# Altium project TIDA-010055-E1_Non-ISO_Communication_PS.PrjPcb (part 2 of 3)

## Sheet TIDA-010055-E1_Non-ISO_Communication_PS_Pg4.SchDoc
size 431 x 279 mm; Date: Not shown in title block; ApprovedBy: Not shown in title block; CheckedBy: Not shown in title block; Author: Not shown in title block; CompanyName: Not shown in title block; Engineer: Not shown in title block; Organization: Not shown in title block; Address1: Not shown in title block; Address2: Not shown in title block; Address3: Not shown in title block; Address4: Not shown in title block; DocumentNumber: 1; Revision: Use project parameter SCH_Rev; SheetNumber: 4; SheetTotal: 7; PageSetup: Record=PageOptions¦CenterHorizontal=True¦CenterVertical=True¦PrintScale=1.00¦XCorrection=1.00¦YCorrection=1.00¦PrintKind=0¦BorderSize=5000000¦LeftOffset=0¦BottomOffset=0¦Orientation=2¦PaperLength=1000¦PaperWidth=1000¦Scale=100¦PaperSource=15¦PrintQuality=600¦MediaType=1¦DitherType=10¦PaperKind=Letter¦PrintScaleMode=1
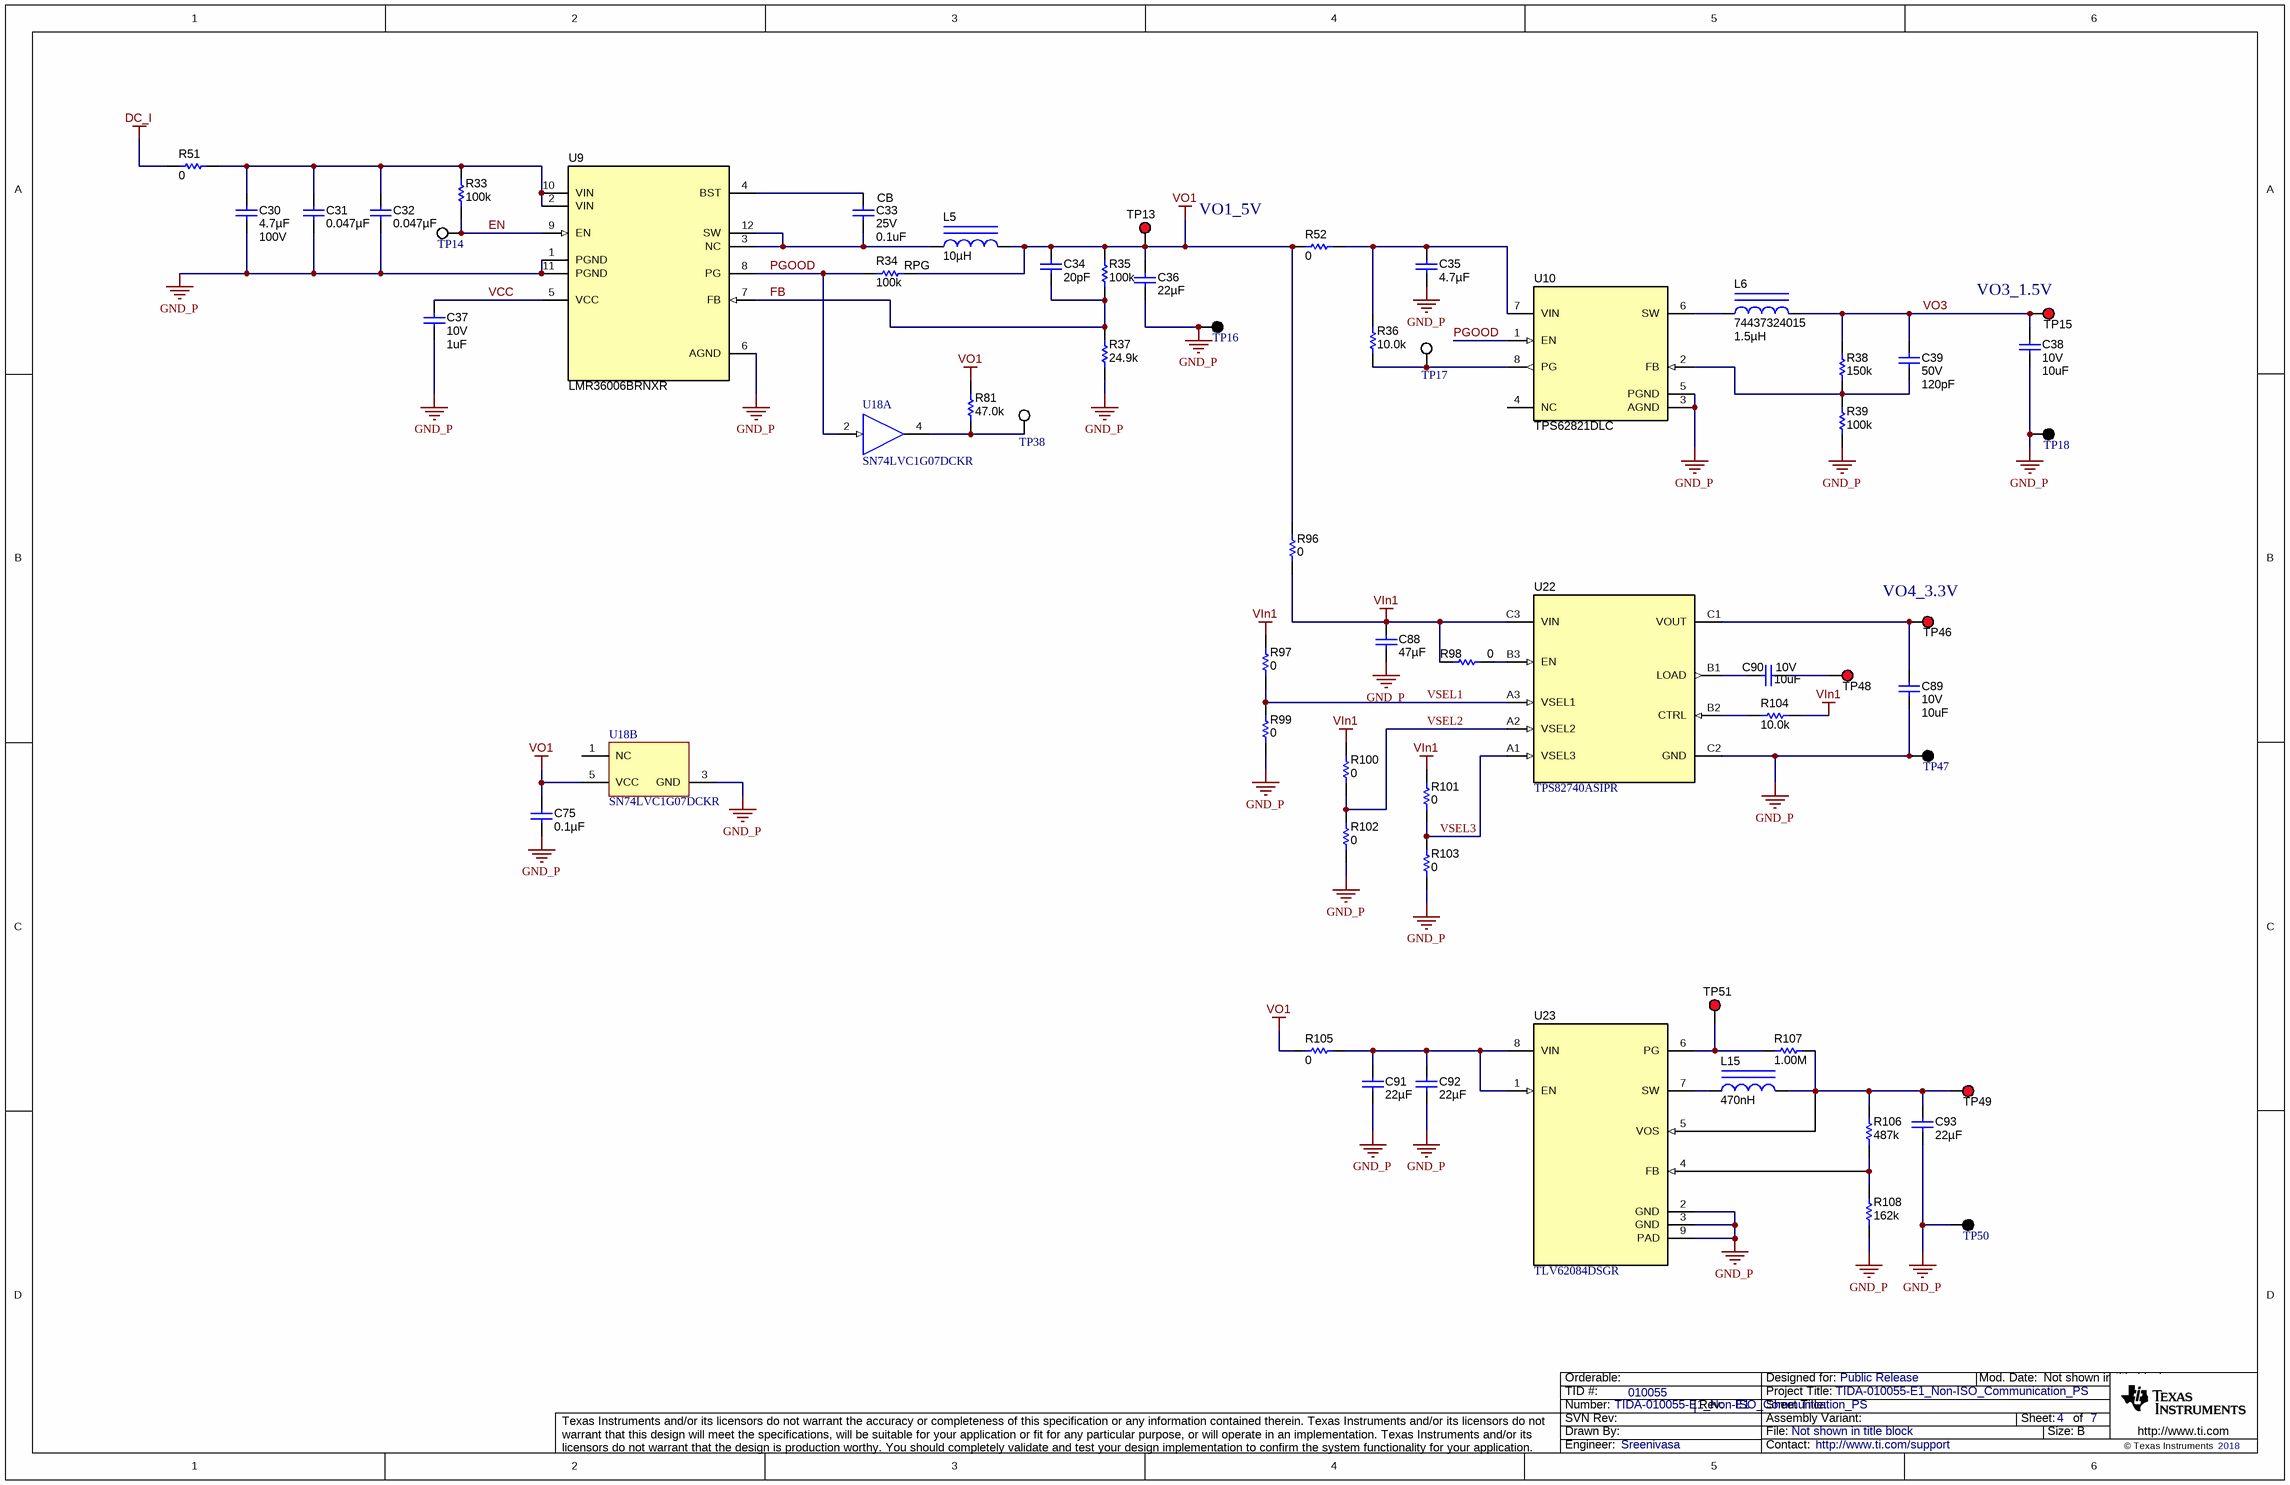
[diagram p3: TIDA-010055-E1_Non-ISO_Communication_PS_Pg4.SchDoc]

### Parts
C30  ValueDisplayed: 4.7µF  Value2: 100V  [1210_220L]  (hidden comment: CIN2)
C31  ValueDisplayed: 0.047µF  [0603L]  (hidden comment: CIN3)
C32  ValueDisplayed: 0.047µF  [0603L]  (hidden comment: CIN1)
C33  CB  VDC_V: 25V  ValueDisplayed: 0.1uF  [0402L]
C34  ValueDisplayed: 20pF  [0402L]  (hidden comment: CFF)
C35  ValueDisplayed: 4.7µF  [0805_HV]  (hidden comment: C2012X7R1A475M125AC)
C36  ValueDisplayed: 22µF  [0805_HV1]  (hidden comment: CL21A226KQCLRNC)
C37  VDC_V: 10V  ValueDisplayed: 1uF  [0402]  (hidden comment: C1005X7S1A105K050BC)
C38  VDC_V: 10V  ValueDisplayed: 10uF  [0805L]  (hidden comment: GRM21BR71A106ME51L)
C39  VDC_V: 50V  ValueDisplayed: 120pF  [0402]  (hidden comment: GRM1555C1H121FA01D)
C75  ValueDisplayed: 0.1µF  [0603]  (hidden comment: C0603C104K5RECAUTO)
C88  ValueDisplayed: 47µF  [1206_190L]  (hidden comment: CL31A476MPHNNNE)
C89  VDC_V: 10V  ValueDisplayed: 10uF  [0805L]  (hidden comment: GRM21BR71A106ME51L)
C90  VDC_V: 10V  ValueDisplayed: 10uF  [0805L]  (hidden comment: GRM21BR71A106ME51L)
C91  ValueDisplayed: 22µF  [0805_HV]  (hidden comment: JMK212BJ226KG-T)
C92  ValueDisplayed: 22µF  [0805_HV]  (hidden comment: JMK212BJ226KG-T)
C93  ValueDisplayed: 22µF  [0805_HV]  (hidden comment: JMK212BJ226KG-T)
L5  ValueDisplayed: 10µH  [WE-MAPI_4030]  (hidden comment: 74438357100)
L6  74437324015  ValueDisplayed: 1.5µH  [IND_WE-LHMI-4020]
L15  ValueDisplayed: 470nH  [VLS2012ET]  (hidden comment: VLS2012ET-R47N)
R33  ValueDisplayed: 100k  [0402L]  (hidden comment: CRCW0402100KFKED)
R34  RPG  ValueDisplayed: 100k  [0402L]
R35  ValueDisplayed: 100k  [0402L]  (hidden comment: CRCW0402100KFKED)
R36  ValueDisplayed: 10.0k  [0402L]  (hidden comment: RPG2)
R37  ValueDisplayed: 24.9k  [0402L]  (hidden comment: CRCW040224K9FKED)
R38  ValueDisplayed: 150k  [0402]  (hidden comment: ERJ-2RKF1503X)
R39  ValueDisplayed: 100k  [0402L]  (hidden comment: RFBB2)
R51  ValueDisplayed: 0  [5108]  (hidden comment: 5108)
R52  ValueDisplayed: 0  [5108]  (hidden comment: 5108)
R81  ValueDisplayed: 47.0k  [0603]  (hidden comment: RG1608P-473-B-T5)
R96  ValueDisplayed: 0  [5108]  (hidden comment: 5108)
R97  ValueDisplayed: 0  [0603]  (hidden comment: CRCW06030000Z0EA)
R98  ValueDisplayed: 0  [0603]  (hidden comment: CRCW06030000Z0EA)
R99  ValueDisplayed: 0  [0603]  (hidden comment: CRCW06030000Z0EA)
R100  ValueDisplayed: 0  [0603]  (hidden comment: CRCW06030000Z0EA)
R101  ValueDisplayed: 0  [0603]  (hidden comment: CRCW06030000Z0EA)
R102  ValueDisplayed: 0  [0603]  (hidden comment: CRCW06030000Z0EA)
R103  ValueDisplayed: 0  [0603]  (hidden comment: CRCW06030000Z0EA)
R104  ValueDisplayed: 10.0k  [0402L]  (hidden comment: RPG2)
R105  ValueDisplayed: 0  [5108]  (hidden comment: 5108)
R106  ValueDisplayed: 487k  [0402]  (hidden comment: CRCW0402487KFKED)
R107  ValueDisplayed: 1.00M  [0402L]  (hidden comment: RC0402FR-071ML)
R108  ValueDisplayed: 162k  [0603L]  (hidden comment: RC0603FR-07162KL)
TP13  5000  [Keystone5000]  (value not drawn)
TP14  5002  [Keystone5002]  (value not drawn)
TP15  5000  [Keystone5000]  (value not drawn)
TP16  5001  [Keystone5001]  (value not drawn)
TP17  5002  [Keystone5002]  (value not drawn)
TP18  5001  [Keystone5001]  (value not drawn)
TP38  5002  [Keystone5002]  (value not drawn)
TP46  5000  [Keystone5000]  (value not drawn)
TP47  5001  [Keystone5001]  (value not drawn)
TP48  5000  [Keystone5000]  (value not drawn)
TP49  5000  [Keystone5000]  (value not drawn)
TP50  5001  [Keystone5001]  (value not drawn)
TP51  5000  [Keystone5000]  (value not drawn)
U9  LMR36006BRNXR  [RNX0012B]
U10  TPS62821DLC  [DLC0008A]
U18  SN74LVC1G07DCKR  [DCK0005A_N]  (parts A,B of 2)
U22  TPS82740ASIPR  [SIP0009F]
U23  TLV62084DSGR  [DSG0008A]

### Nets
DC_I: R51.2
GND_P: C30.1 C31.2 C32.2 C35.2 C36.2 C37.2 C38.2 C75.2 C88.2 C89.2 C91.2 C92.2 C93.2 R37.1 R39.1 R99.1 R102.1 R103.1 R108.1 TP16.1 TP18.1 TP47.1 TP50.1 U9.1(PGND) U9.6(AGND) U9.11(PGND) U10.3(AGND) U10.5(PGND) U18.3(GND) U22.C2(GND) U23.2(GND) U23.3(GND) U23.9(PAD)
VIn1: C88.1 R96.2 R97.2 R98.1 R100.2 R101.2 R104.1 U22.C3(VIN)
VO1: C34.1 C36.1 C75.1 L5.2 R34.1 R35.2 R52.2 R81.2 R96.1 R105.1 TP13.1 U18.5(VCC)
EN: R33.1 TP14.1 U9.9(EN)
FB: C34.2 R35.1 R37.2 U9.7(FB)
PGOOD: R34.2 U9.8(PG) U10.1(EN) U18.2(A)
VCC: C37.1 U9.5(VCC)
VO3: C38.1 C39.1 L6.2 R38.2 TP15.1
VSEL1: R97.1 R99.2 U22.A3(VSEL1)
VSEL2: R100.1 R102.2 U22.A2(VSEL2)
VSEL3: R101.1 R103.2 U22.A1(VSEL3)
NetC30_2: C30.2 C31.1 C32.1 R33.2 R51.1 U9.2(VIN) U9.10(VIN)
NetC33_1: C33.1 U9.4(BST)
NetC33_2: C33.2 L5.1 U9.3(NC) U9.12(SW)
NetC35_1: C35.1 R36.2 R52.1 U10.7(VIN)
NetC39_2: C39.2 R38.1 R39.2 U10.2(FB)
NetC89_1: C89.1 TP46.1 U22.C1(VOUT)
NetC90_1: C90.1 U22.B1(LOAD)
NetC90_2: C90.2 TP48.1
NetC91_1: C91.1 C92.1 R105.2 U23.1(EN) U23.8(VIN)
NetC93_1: C93.1 L15.2 R106.2 R107.2 TP49.1 U23.5(VOS)
NetL6_1: L6.1 U10.6(SW)
NetL15_1: L15.1 U23.7(SW)
NetR36_1: R36.1 TP17.1 U10.8(PG)
NetR81_1: R81.1 TP38.1 U18.4(Y)
NetR98_2: R98.2 U22.B3(EN)
NetR104_2: R104.2 U22.B2(CTRL)
NetR106_1: R106.1 R108.2 U23.4(FB)
NetR107_1: R107.1 TP51.1 U23.6(PG)

Not connected (* = marked no-connect by the designer): U10 4(NC); U18 1(NC)

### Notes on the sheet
- VO1_5V
- (near TP15) VO3_1.5V
- (near TP46) VO4_3.3V

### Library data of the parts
C30 = CGA6M3X7S2A475K200AB: CAP, CERM, 4.7 µF, 100 V, +/- 10%, X7S, AEC-Q200 Grade 1, 1210; Manufacturer: TDK; Polarized: N; CompType: Capacitor; Value: 4.7uF; U/M: EA; Cap_F: 0.0000047; Tolerance_%: 10; ESR_ohm: 0.004236; Value1: 0.004236 ohm; VDC_V: 100; IRMS_A: 3.57337; TaMin_C: -55; TaMax_C: 125; Cap_Case: 1210_220; SizeArea_mm2: 8; SizeAreaWB_mm2: 14.7; SizeX_mm: 3.2; SizeY_mm: 2.5; SizeZ_mm: 2.2; AEC Category: Q200; AEC Qualified: Y; AEC Grade: 1
C31 C32 = CGA3E3X7S2A473K080AB: CAP, CERM, 0.047 µF, 100 V,+/- 10%, X7S, AEC-Q200 Grade 1, 0603; Manufacturer: TDK; Polarized: N; CompType: Capacitor; Value: 0.047uF; U/M: EA; Cap_F: 0.000000047; Tolerance_%: 10; ESR_ohm: 0.089796; Value1: 0.089796 ohm; VDC_V: 100; Value2: 100V; IRMS_A: 0.567484; TaMin_C: -55; TaMax_C: 125; Cap_Case: 0603; SizeArea_mm2: 1.28; SizeAreaWB_mm2: 4.68; SizeX_mm: 1.6; SizeY_mm: 0.8; SizeZ_mm: 1; AEC Category: Q200; AEC Qualified: Y
C33 = CMP-0006659-2: CAP, CERM, 0.1 uF, 25 V, +/- 10%, X7R, 0402; Manufacturer: MuRata; PartNumber: GRM155R71E104KE14D; TaMin_C: -55°C; Polarized: N; SizeAreaWB_mm2: 3; Value1: Unknown; U/M: EA; Value: 0.1uF; TaMax_C: 125°C; SizeZ_mm: 0.6; SizeX_mm: 1; SizeY_mm: 0.5; Cap_Case: 0402; CompType: Capacitor; Cap_F: 100nF; AEC Category: Q200
C34 = GRM1555C1E200JA01D: CAP, CERM, 20 pF, 25 V,+/- 5%, C0G/NP0, 0402; Manufacturer: MuRata; Polarized: N; CompType: Capacitor; Value: 20pF; U/M: EA; Cap_F: 0.00000000002; Tolerance_%: 5; VDC_V: 25; Value2: 25V; TaMin_C: -55; TaMax_C: 125; Cap_Case: 0402; SizeArea_mm2: 0.5; SizeAreaWB_mm2: 3; SizeX_mm: 1; SizeZ_mm: 0.6; AEC Category: Q200
C35 = C2012X7R1A475M125AC: CAP, CERM, 4.7 µF, 10 V,+/- 20%, X7R, 0805; Manufacturer: TDK; Polarized: N; CompType: Capacitor; Value: 4.7uF; U/M: EA; Cap_F: 0.0000047; Tolerance_%: 20; VDC_V: 10; Value2: 10V; TaMin_C: -55; TaMax_C: 125; Cap_Case: 0805; SizeArea_mm2: 2.5; SizeAreaWB_mm2: 6.75; SizeX_mm: 2; SizeY_mm: 1.25; SizeZ_mm: 1.45; AEC Category: Q200; Green_Lifecycle: Active; Green_REACh: Passed
C36 = GRM21BR60J226ME39L: CAP, CERM, 22 µF, 6.3 V, +/- 20%, X5R, 0805; Manufacturer: Samsung Electro-Mechanics; Polarized: N; CompType: Capacitor; Value: 22uF; U/M: EA; Cap_F: 0.000022; Tolerance_%: 20; ESR_ohm: 0.009; Value1: 0.009 ohm; VDC_V: 6.3; Value2: 6.3V; IRMS_A: 3.5; TaMin_C: -55; TaMax_C: 85; Cap_Case: 0805; AEC Category: Q200
C37 = CMP-0006300-2: CAP, CERM, 1 uF, 10 V, +/- 10%, X7S, 0402; Manufacturer: Murata Electronics North America; PartNumber: GCM155C71A105KE38D; TaMin_C: -55°C; ESR_ohm: 0.011416; Polarized: N; SizeAreaWB_mm2: 3; Value1: 0.011416 ohm; U/M: EA; Value: 1uF; TaMax_C: 125°C; SizeZ_mm: 0.6; SizeX_mm: 1; SizeY_mm: 0.5; CompType: Capacitor; Cap_F: 1µF; IRMS_A: 1.483A; AEC Category: Q200
C38 C89 C90 = CMP-0008316-2: CAP, CERM, 10 uF, 10 V, +/- 20%, X7R, 0805; Manufacturer: TDK Corporation; PartNumber: C2012X7R1A106M125AC; TaMin_C: -55°C; Polarized: N; SizeAreaWB_mm2: 6.75; Value1: Unknown; U/M: EA; Value: 10uF; TaMax_C: 125°C; SizeZ_mm: 1.45; SizeX_mm: 2; SizeY_mm: 1.25; Cap_Case: 0805; SizeArea_mm2: 2.5; CompType: Capacitor; Cap_F: 10µF; AEC Category: Q200
C39 = CMP-0006416-2: CAP, CERM, 120 pF, 50 V, +/- 1%, C0G/NP0, 0402; Manufacturer: Samsung Electro-Mechanics; PartNumber: CL05C121JB5NNNC; TaMin_C: -55°C; Polarized: N; SizeAreaWB_mm2: 3; Value1: Unknown; U/M: EA; Value: 120pF; TaMax_C: 125°C; SizeZ_mm: 0.6; SizeX_mm: 1; SizeY_mm: 0.5; CompType: Capacitor; AEC Category: Q200
C75 = C0603C104K5RACTU: CAP, CERM, 0.1µF ±10% 50V Ceramic Capacitor X7R 0603; Manufacturer: Kemet; Polarized: N; Value: 0.1uF; U/M: EA; Cap_F: 0.0000001; Tolerance_%: 10; VDC_V: 50; TaMin_C: -55; TaMax_C: 125; SizeArea_mm2: 1.28; SizeAreaWB_mm2: 4.68; SizeX_mm: 1.6; SizeY_mm: 0.8; SizeZ_mm: 1; AEC Category: Q200; Green_Lifecycle: Active; Green_REACh: Passed
C88 = C3216X5R1E476M160AC: CAP, CERM, 47 µF, 25 V,+/- 20%, X5R, 1206; Manufacturer: Samsung Electro-Mechanics; Polarized: N; CompType: Capacitor; Value: 47uF; U/M: EA; Cap_F: 0.000047; Tolerance_%: 20; VDC_V: 25; Value2: 25V; TaMin_C: -55; TaMax_C: 85; Cap_Case: 1206; SizeArea_mm2: 5.12; SizeAreaWB_mm2: 10.92; SizeX_mm: 3.2; SizeY_mm: 1.6; SizeZ_mm: 1.9; AEC Category: Q200; Green_Lifecycle: Active; Green_REACh: Passed
C91-C93 = JMK212BJ226KG-T: CAP, CERM, 22 µF, 6.3 V,+/- 10%, X5R, 0805; Manufacturer: Taiyo Yuden; Polarized: N; CompType: Capacitor; Value: 22uF; U/M: EA; Cap_F: 0.000022; Tolerance_%: 10; ESR_ohm: 0.002; Value1: 0.002 ohm; VDC_V: 6.3; Value2: 6.3V; TaMin_C: -55; TaMax_C: 85; Cap_Case: 0805; AEC Category: Q200; SizeArea_mm2: 2.5; SizeAreaWB_mm2: 6.75; SizeX_mm: 2; SizeY_mm: 1.25; SizeZ_mm: 1.45; Green_Lifecycle: Not Set; Green_REACh: Incomplete
L5 = CMP-0081728-1: Inductor, Shielded, Metal Composite, 10 µH, 2.7 A, 0.11 ohm, SMD; Manufacturer: Wurth Elektronik; SizeAreaWB_mm2: 26.01; Irms: 2.7A @ 40C rise; SizeArea_mm2: 16.81; AEC Qualified: N; AEC Category: Q200; Value: 10uH; SizeZ_mm: 3.1; Imax_A: 2.7A; SizeY_mm: 4.1; Isat: 4.6A @ 20% inductance drop; DCR_ohm: 0.11
L6 = 74437324015: Inductor, Shielded Drum Core, Powdered Iron, 1.5uH, 3.8A, 0.0348 ohm, SMD; Manufacturer: Wurth Elektronik eiSos; Ind_H: 1.5E-6; Imax_A: 3.8; Irms: 3.8A @ 40C rise; Isat: 8A @ 20% inductance drop; DCR_ohm: 0.0348; U/M: EA
L15 = VLS2012ET-R47N: Inductor, Shielded Drum Core, Ferrite, 470 nH, 2 A, 0.059 ohm, SMD; Manufacturer: TDK; Value: 470nH; Ind_H: 470.0E-9; Imax_A: 2; Irms: 2A @ 40C rise; Isat: 2.25A @ 30% inductance drop; DCR_ohm: 0.059; Value2: 2A; AEC Category: Q200
R33-R35 = CRCW0402100KFKED: RES, 100 k, 1%, 0.063 W, 0402; Manufacturer: Vishay-Dale; CompType: Resistor; Value: 100k; Res_ohm: 100000; Tolerance_%: 1; Power_W: 0.063; Value2: 0.063W; VDC_V: 50; TempCo: 100 ppm/C; SizeArea_mm2: 0.5; SizeZ_mm: 0.6; EIA_Code: E96; U/M: EA; AEC Category: Q200; Green_Lifecycle: Active; Green_REACh: Passed
R36 R104 = CMP-0025958-2: RES, 10.0 k, 1%, 0.063 W, 0402; Manufacturer: Vishay-Dale; PartNumber: CRCW040210K0FKED; Power_W: 63mW; TempCo: 100 ppm/C; Value_Code: 10k0; U/M: EA; Value: 10.0k; EIA_Code: E96; Res_ohm: 10k; SizeX_mm: 1; SizeY_mm: 0.5; SizeZ_mm: 0.6; Value2: 0.063W; CompType: Resistor; VDC_V: 50V; AEC Category: Q200
R37 = CMP-0026196-1: RES, 24.9 k, 1%, 0.063 W, 0402; Manufacturer: Vishay-Dale; Power_W: 63mW; TempCo: 100 ppm/C; Value_Code: 24k9; U/M: EA; Value: 24.9k; EIA_Code: E96; SizeX_mm: 1; SizeY_mm: 0.5; SizeZ_mm: 0.6; Value2: 0.063W; CompType: Resistor; VDC_V: 50V; AEC Category: Q200
R38 = CMP-0026669-1: RES, 150 k, 1%, 0.1 W, AEC-Q200 Grade 0, 0402; Manufacturer: Panasonic; Power_W: 100mW; TempCo: 100 ppm/C; U/M: EA; Value: 150k; EIA_Code: E96; SizeX_mm: 1; SizeY_mm: 0.5; SizeZ_mm: 0.6; Value2: 0.1W; CompType: Resistor; AEC Qualified: Y; VDC_V: 50V; AEC Grade: 0; AEC Category: Q200
R39 = CMP-0025950-2: RES, 100 k, 1%, 0.063 W, 0402; Manufacturer: Vishay-Dale; PartNumber: CRCW0402100KFKED; Power_W: 63mW; TempCo: 100 ppm/C; U/M: EA; Value: 100k; EIA_Code: E96; SizeX_mm: 1; SizeY_mm: 0.5; SizeZ_mm: 0.6; Value2: 0.063W; CompType: Resistor; VDC_V: 50V; AEC Category: Q200
R51 R52 R96 R105 = 5108: RES, 0, 1%, 0.5 W, 1206; Manufacturer: Keystone; CompType: Resistor; Value: 0; Tolerance_%: 1; Power_W: 0.5; Value2: 0.5W; TempCo: ppm/C; SizeArea_mm2: 5.185; SizeX_mm: 3.05; SizeY_mm: 1.7; SizeZ_mm: 0.84; U/M: EA; AEC Category: Q200; AEC Qualified: N
R81 = RG1608P-473-B-T5: RES, 47.0 k, 0.1%, 0.1 W, 0603; Manufacturer: Susumu Co Ltd; CompType: Resistor; Value: 47.0k; Res_ohm: 47000; Value_Code: 47k0; Tolerance_%: 0.1; Value2: 0.1W; VDC_V: 75; TempCo: 25 ppm/C; SizeArea_mm2: 1.28; SizeX_mm: 1.6; SizeY_mm: 0.8; SizeZ_mm: 1; EIA_Code: E192; U/M: EA; AEC Category: Q200
R97-R103 = CRCW06030000Z0EA: RES, 0, 5%, 0.1 W, 0603; Manufacturer: Vishay-Dale; CompType: Resistor; Value: 0; Value_Code: 0000; Tolerance_%: 5; Power_W: 0.1; Value2: 0.1W; VDC_V: 75; TempCo: 200 ppm/C; EIA_Code: E24; U/M: EA; AEC Category: Q200
R106 = CRCW0402487KFKED: RES, 487 k, 1%, 0.063 W, 0402; Manufacturer: Vishay-Dale; CompType: Resistor; Value: 487k; Res_ohm: 487000; Tolerance_%: 1; Power_W: 0.063; Value2: 0.063W; VDC_V: 50; TempCo: 100 ppm/C; SizeArea_mm2: 0.5; SizeZ_mm: 0.6; EIA_Code: E96; U/M: EA; AEC Category: Q200; Green_Lifecycle: Active; Green_REACh: Passed
R107 = RC0402FR-071ML: RES, 1.00 M, 1%, 0.063 W, 0402; Manufacturer: Yageo America; CompType: Resistor; Value: 1.00Meg; Res_ohm: 1000000; Value_Code: 1M00; Tolerance_%: 1; Power_W: 0.063; Value2: 0.063W; TempCo: 100 ppm/C; EIA_Code: E96; U/M: EA; AEC Category: Q200; SizeArea_mm2: 0.5; SizeZ_mm: 0.6; Green_Lifecycle: Active; Green_REACh: Passed
R108 = RC0603FR-07162KL: RES, 162 k, 1%, 0.1 W, 0603; Manufacturer: Yageo America; CompType: Resistor; Value: 162k; Res_ohm: 162000; Tolerance_%: 1; Power_W: 0.1; Value2: 0.1W; VDC_V: 150; TempCo: 200 ppm/C; EIA_Code: E96; U/M: EA; AEC Category: Q200; SizeArea_mm2: 1.28; SizeX_mm: 1.6; SizeY_mm: 0.8; Green_Lifecycle: Active; Green_REACh: Passed
TP13 TP15 TP46 TP48 TP49 TP51 = 5000: Test Point, Miniature, Red, TH; Manufacturer: Keystone; CompType: Test Point Loop; ContactFinish: Silver
TP14 TP17 TP38 = 5002: Test Point, Miniature, White, TH; Manufacturer: Keystone; CompType: Test Point Loop; ContactFinish: Silver; Green_Lifecycle: Active; Green_REACh: Passed
TP16 TP18 TP47 TP50 = 5001: Test Point, Miniature, Black, TH; Manufacturer: Keystone; CompType: Test Point Loop; ContactFinish: Silver; Green_Lifecycle: Active; Green_REACh: Passed
U9 = CMP-0077274-3: 65-V 0.6-A Synchronous Step-Down Converter, RNX0012B (VQFN-HR-12); Alternate PartNumber: LMR36006BRNXT; Alternate Manufacturer: Texas Instruments; SizeAreaWB_mm2: 12.0; SizeZ_mm: 1.0; SizeX_mm: 2.0; SizeY_mm: 3.0; SizeArea_mm2: 6.0; CompType: IC; AEC Qualified: N; AEC Category: Q200
U10 = CMP-0065148-2: 2.5-V to 5.5-V, 1-, 2-, 3-A Step-Down Converter with DCS-Control, DLC0008A (SON-HR-8); Manufacturer: Texas Instruments; SizeX_mm: 1.5; SizeY_mm: 2.0; CompType: IC; SizeZ_mm: 1.0; SizeArea_mm2: 3.0; SizeAreaWB_mm2: 7.5; U/M: EA
U18 = CMP-0051390-2: Single Buffer/Driver With Open-Drain Output, DCK0005A, LARGE T&R; Manufacturer: Texas Instruments; 3-State Output: No; F @ Nom Voltage(Max)(Mhz): 150; ICC @ Nom Voltage(Max)(mA): 0.01; VCC(Min)(V): 1.65; Logic: True; Sub-Family: Non-Inverting Buffer/Driver; Output Drive (IOL/IOH)(Max)(mA): 32/-32; Input Type: CMOS/TTL; Technology Family: LVC; Bits(#): 1; VCC(Max)(V): 5.5; Output Type: CMOS; tpd @ Nom Voltage(Max)(ns): 8.6,6,4.7,4; Rating: Catalog; Voltage(Nom)(V): 1.8,2.5,3.3,5; AEC Category: Q200; AEC Qualified: N; CompType: IC; SizeAreaWB_mm2: 9.3; SizeArea_mm2: 4.2; SizeX_mm: 2.1; SizeY_mm: 2.0; SizeZ_mm: 1.1
U22 = CMP-0067293-1: 200-mA Step Down Converter MicroSiP Module with 360nA quiescent current, SIP0009F (uSIP-9); Alternate PartNumber: TPS82740ASIPT; Alternate Manufacturer: Texas Instruments; SizeAreaWB_mm2: 13.2325; U/M: EA; SizeZ_mm: 1.1; SizeX_mm: 2.95; SizeY_mm: 2.35; SizeArea_mm2: 6.9325; CompType: IC
U23 = CMP-0067001-2: 2A High Efficient Step Down Converter in 2x2mm SON Package, TLV62084, DSG0008A (WSON-8); Alternate PartNumber: TLV62084DSGT; Manufacturer: Texas Instruments; SizeZ_mm: 0.8; SizeX_mm: 2.0; SizeArea_mm2: 4.0; CompType: IC; U/M: EA; SizeAreaWB_mm2: 9.0

## Sheet TIDA-010055-E1_Non-ISO_Communication_PS_Pg5.SchDoc
size 431 x 279 mm; Date: Not shown in title block; ApprovedBy: Not shown in title block; CheckedBy: Not shown in title block; Author: Not shown in title block; CompanyName: Not shown in title block; Engineer: Not shown in title block; Organization: Not shown in title block; Address1: Not shown in title block; Address2: Not shown in title block; Address3: Not shown in title block; Address4: Not shown in title block; DocumentNumber: 1; Revision: Use project parameter SCH_Rev; SheetNumber: 5; SheetTotal: 7; PageSetup: Record=PageOptions¦CenterHorizontal=True¦CenterVertical=True¦PrintScale=1.00¦XCorrection=1.00¦YCorrection=1.00¦PrintKind=0¦BorderSize=5000000¦LeftOffset=0¦BottomOffset=0¦Orientation=2¦PaperLength=1000¦PaperWidth=1000¦Scale=100¦PaperSource=15¦PrintQuality=600¦MediaType=1¦DitherType=10¦PaperKind=Letter¦PrintScaleMode=1
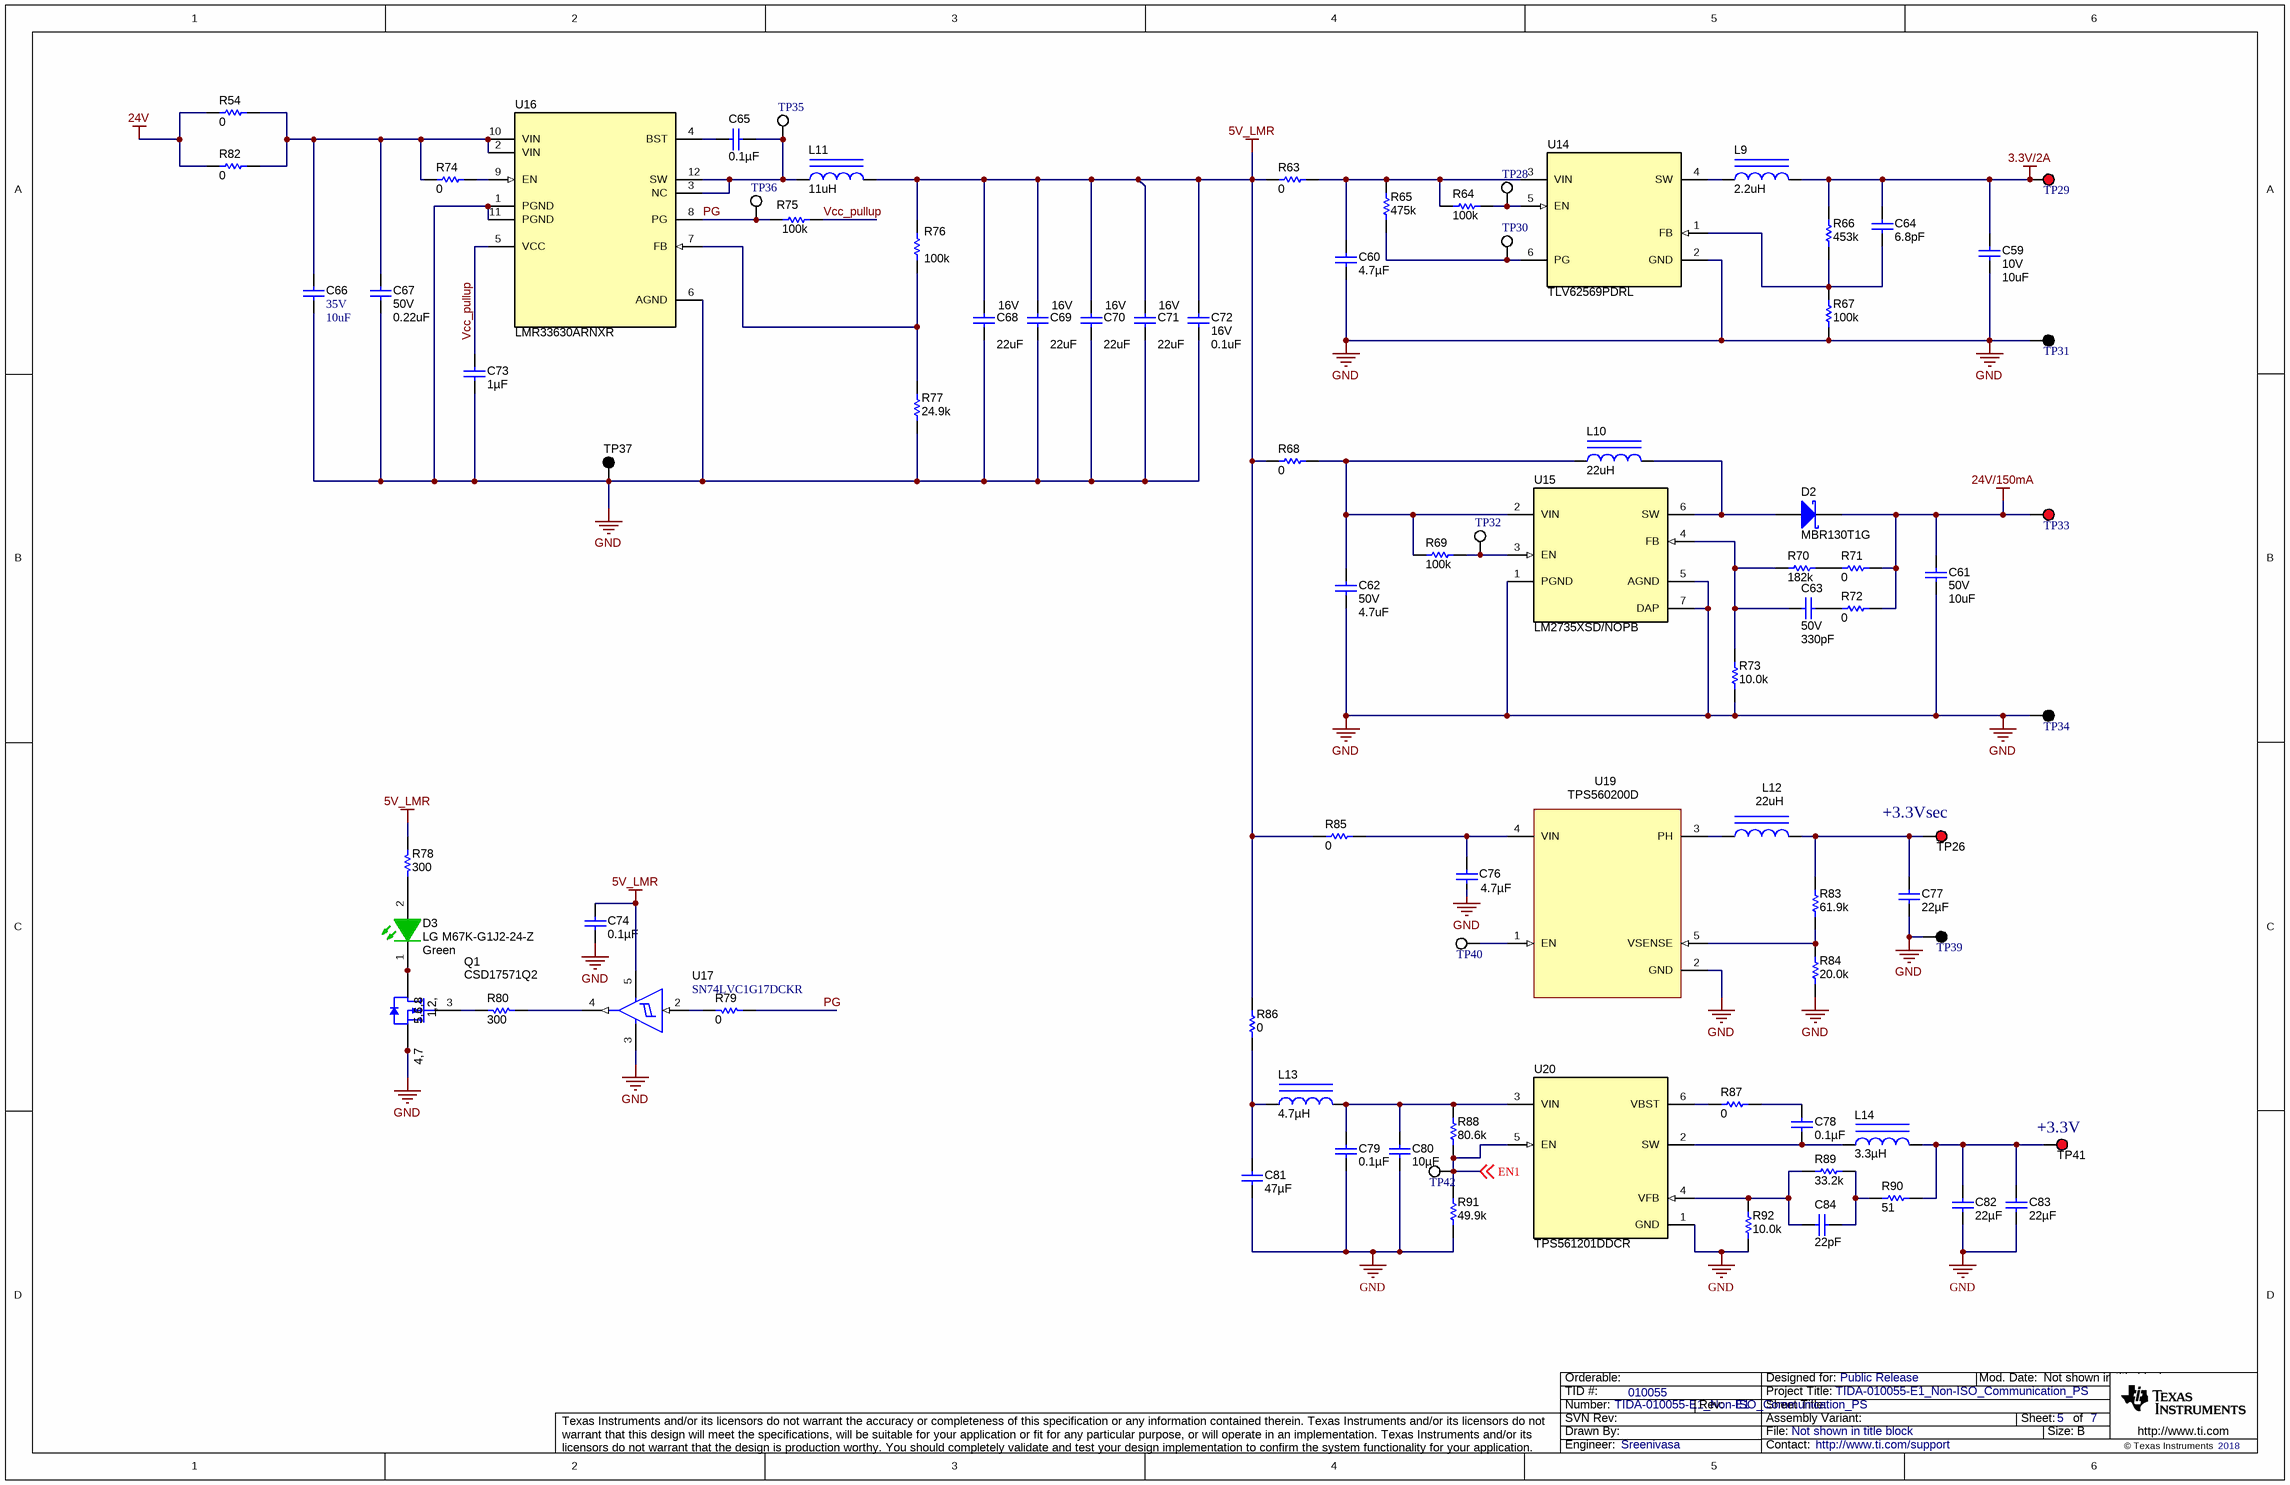
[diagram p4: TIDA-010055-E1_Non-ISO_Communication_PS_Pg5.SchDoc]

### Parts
C59  VDC_V: 10V  ValueDisplayed: 10uF  [0805_HV]  (hidden comment: GRM21BR71A106KE51L)
C60  ValueDisplayed: 4.7µF  [0805_HV]  (hidden comment: C2012X7R1V475K125AC)
C61  VDC_V: 50V  ValueDisplayed: 10uF  [1206_180]  (hidden comment: CL31B106KBHNNNE)
C62  VDC_V: 50V  ValueDisplayed: 4.7uF  [1206_190]  (hidden comment: UMK316AB7475KL-T)
C63  VDC_V: 50V  ValueDisplayed: 330pF  [0603]  (hidden comment: GRM188R71H331KA01D)
C64  ValueDisplayed: 6.8pF  [0603]  (hidden comment: 06035A6R8CAT2A)
C65  ValueDisplayed: 0.1µF  [0603]  (hidden comment: CL10B104KB8NNNC)
C66  VDC_V: 35V  ValueDisplayed: 10uF  [1206_180]  (hidden comment: C3216X7R1V106K160AC)
C67  VDC_V: 50V  ValueDisplayed: 0.22uF  [0805_HV]  (hidden comment: UMK212B7224KG-T)
C68  VDC_V: 16V  ValueDisplayed: 22uF  [1206_190]  (hidden comment: EMK316BB7226ML-T)
C69  VDC_V: 16V  ValueDisplayed: 22uF  [1206_190]  (hidden comment: EMK316BB7226ML-T)
C70  VDC_V: 16V  ValueDisplayed: 22uF  [1206_190]  (hidden comment: EMK316BB7226ML-T)
C71  VDC_V: 16V  ValueDisplayed: 22uF  [1206_190]  (hidden comment: EMK316BB7226ML-T)
C72  VDC_V: 16V  ValueDisplayed: 0.1uF  [0603]  (hidden comment: EMK107B7104KA-T)
C73  ValueDisplayed: 1µF  [0603]  (hidden comment: 885012206052)
C74  ValueDisplayed: 0.1µF  [0603]  (hidden comment: GMK107BJ104KAHT)
C76  ValueDisplayed: 4.7µF  [0805_HV]  (hidden comment: C2012X5R1E475K125AB)
C77  ValueDisplayed: 22µF  [0805_HV]  (hidden comment: CL21A226KQCLRNC)
C78  ValueDisplayed: 0.1µF  [0603]  (hidden comment: C0603C104K9RAC7867)
C79  ValueDisplayed: 0.1µF  [0603]  (hidden comment: 885012206071)
C80  ValueDisplayed: 10µF  [1206]  (hidden comment: GMK316AB7106KL)
C81  ValueDisplayed: 47µF  [1206_190L]  (hidden comment: CL31A476MPHNNNE)
C82  ValueDisplayed: 22µF  [0805_HV]  (hidden comment: CL21A226MPCLRNC)
C83  ValueDisplayed: 22µF  [0805_HV]  (hidden comment: CL21A226MPCLRNC)
C84  ValueDisplayed: 22pF  [0603]  (hidden comment: CL10C220JB8NNNC)
D2  MBR130T1G  [SOD-123]
D3  LG M67K-G1J2-24-Z  value Green  [LG_M67K_Green]
L9  ValueDisplayed: 2.2uH  [LQH5BPN_20]  (hidden comment: LQH5BPN2R2NT0L)
L10  ValueDisplayed: 22uH  [WE-TIS-1111]  (hidden comment: 7447471220)
L11  ValueDisplayed: 11uH  [WE-PDF_1064]  (hidden comment: 7447798111)
L12  value 22uH  [WE-SPC_4838]  (hidden comment: 74408943220)
L13  ValueDisplayed: 4.7µH  [ABG03A15]  (hidden comment: ABG03A15M4R7)
L14  ValueDisplayed: 3.3µH  [ABG06A45]  (hidden comment: ABG06A45M3R3)
Q1  CSD17571Q2  [DQK0006C]
R54  ValueDisplayed: 0  [5108]  (hidden comment: 5108)
R63  ValueDisplayed: 0  [5108]  (hidden comment: 5108)
R64  ValueDisplayed: 100k  [0603]  (hidden comment: ERA-3AEB104V)
R65  ValueDisplayed: 475k  [0805_HV]  (hidden comment: RR1220P-4753-D-M)
R66  ValueDisplayed: 453k  [0603]  (hidden comment: RC0603FR-07453KL)
R67  ValueDisplayed: 100k  [0603]  (hidden comment: ERA-3AEB104V)
R68  ValueDisplayed: 0  [5108]  (hidden comment: 5108)
R69  ValueDisplayed: 100k  [0603]  (hidden comment: ERA-3AEB104V)
R70  ValueDisplayed: 182k  [0805_HV]  (hidden comment: RT0805BRD07182KL)
R71  ValueDisplayed: 0  [0603]  (hidden comment: RMCF0603ZT0R00)
R72  ValueDisplayed: 0  [0603]  (hidden comment: RMCF0603ZT0R00)
R73  ValueDisplayed: 10.0k  [0603]  (hidden comment: RG1608P-103-B-T5)
R74  ValueDisplayed: 0  [0603]  (hidden comment: RMCF0603ZT0R00)
R75  ValueDisplayed: 100k  [0603]  (hidden comment: ERA-3AEB104V)
R76  ValueDisplayed: 100k  [0603]  (hidden comment: ERA-3AEB104V)
R77  ValueDisplayed: 24.9k  [0603]  (hidden comment: RT0603BRD0724K9L)
R78  ValueDisplayed: 300  [0603]  (hidden comment: CRCW0603300RJNEA)
R79  ValueDisplayed: 0  [0603]  (hidden comment: RMCF0603ZT0R00)
R80  ValueDisplayed: 300  [0603]  (hidden comment: CRCW0603300RJNEA)
R82  ValueDisplayed: 0  [5108]  (hidden comment: 5108)
R83  ValueDisplayed: 61.9k  [0603]  (hidden comment: CRCW060361K9FKEA)
R84  ValueDisplayed: 20.0k  [0603]  (hidden comment: CRCW060320K0FKEA)
R85  ValueDisplayed: 0  [5108]  (hidden comment: 5108)
R86  ValueDisplayed: 0  [5108]  (hidden comment: 5108)
R87  ValueDisplayed: 0  [0603]  (hidden comment: CRCW06030000Z0EA)
R88  ValueDisplayed: 80.6k  [0603]  (hidden comment: CRCW060380K6FKEA)
R89  ValueDisplayed: 33.2k  [0603]  (hidden comment: CRCW060333K2FKEA)
R90  ValueDisplayed: 51  [0603]  (hidden comment: CRCW060351R0JNEA)
R91  ValueDisplayed: 49.9k  [0603]  (hidden comment: CRCW060349K9FKEA)
R92  ValueDisplayed: 10.0k  [0603]  (hidden comment: RCG060310K0FKEA)
TP26  5000  [Keystone5000]  (value not drawn)
TP28  5002  [Keystone5002]  (value not drawn)
TP29  5000  [Keystone5000]  (value not drawn)
TP30  5002  [Keystone5002]  (value not drawn)
TP31  5001  [Keystone5001]  (value not drawn)
TP32  5002  [Keystone5002]  (value not drawn)
TP33  5000  [Keystone5000]  (value not drawn)
TP34  5001  [Keystone5001]  (value not drawn)
TP35  5002  [Keystone5002]  (value not drawn)
TP36  5002  [Keystone5002]  (value not drawn)
TP37  5001  [Keystone5001]  (value not drawn)
TP39  5001  [Keystone5001]  (value not drawn)
TP40  5002  [Keystone5002]  (value not drawn)
TP41  5000  [Keystone5000]  (value not drawn)
TP42  5002  [Keystone5002]  (value not drawn)
U14  TLV62569PDRL  [DRL0006A]
U15  LM2735XSD/NOPB  [NGG0006A]
U16  LMR33630ARNXR  [RNX0012B]
U17  SN74LVC1G17DCKR  [DCK0005A_N]
U19  value TPS560200D  [DBV0005A_N]  (hidden comment: TPS560200DBVR)
U20  TPS561201DDCR  [DDC0006A_N]

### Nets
3.3V/2A: C59.1 C64.1 L9.2 R66.2 TP29.1
5V_LMR: C68.1 C69.1 C70.1 C71.1 C72.1 C74.1 L11.2 R63.1 R68.1 R76.2 R78.2 R85.1 R86.1 U17.5(VCC)
24V: R54.2 R82.2
24V/150mA: C61.1 D2.1(K) R71.1 R72.1 TP33.1
GND: C59.2 C60.2 C61.2 C62.2 C66.2 C67.2 C68.2 C69.2 C70.2 C71.2 C72.2 C73.2 C74.2 C76.2 C77.2 C79.2 C80.2 C81.2 C82.2 C83.2 Q1.4(S) Q1.7(S) R67.1 R73.1 R77.1 R84.1 R91.1 R92.1 TP31.1 TP34.1 TP37.1 TP39.1 U14.2(GND) U15.1(PGND) U15.5(AGND) U15.7(DAP) U16.1(PGND) U16.6(AGND) U16.11(PGND) U17.3(GND) U19.2(GND) U20.1(GND)
EN1: R88.1 R91.2 TP42.1 U20.5(EN) ; off-sheet EN1
PG: R75.2 R79.1 TP36.1 U16.8(PG)
Vcc_pullup: C73.1 R75.1 U16.5(VCC)
NetC60_1: C60.1 R63.2 R64.1 R65.2 U14.3(VIN)
NetC62_1: C62.1 L10.1 R68.2 R69.1 U15.2(VIN)
NetC63_1: C63.1 R70.1 R73.2 U15.4(FB)
NetC63_2: C63.2 R72.2
NetC64_2: C64.2 R66.1 R67.2 U14.1(FB)
NetC65_1: C65.1 U16.4(BST)
NetC65_2: C65.2 L11.1 TP35.1 U16.3(NC) U16.12(SW)
NetC66_1: C66.1 C67.1 R54.1 R74.2 R82.1 U16.2(VIN) U16.10(VIN)
NetC76_1: C76.1 R85.2 U19.4(VIN)
NetC77_1: C77.1 L12.2 R83.2 TP26.1
NetC78_1: C78.1 R87.2
NetC78_2: C78.2 L14.1 U20.2(SW)
NetC79_1: C79.1 C80.1 L13.2 R88.2 U20.3(VIN)
NetC81_1: C81.1 L13.1 R86.2
NetC82_1: C82.1 C83.1 L14.2 R90.2 TP41.1
NetC84_1: C84.1 R89.2 R90.1
NetC84_2: C84.2 R89.1 R92.2 U20.4(VFB)
NetD2_2: D2.2(A) L10.2 U15.6(SW)
NetD3_1: D3.1(K) Q1.1(D) Q1.2(D) Q1.5(D) Q1.6(D) Q1.8(D)
NetD3_2: D3.2(A) R78.1
NetL9_1: L9.1 U14.4(SW)
NetL12_1: L12.1 U19.3(PH)
NetQ1_3: Q1.3(G) R80.1
NetR64_2: R64.2 TP28.1 U14.5(EN)
NetR65_1: R65.1 TP30.1 U14.6(PG)
NetR69_2: R69.2 TP32.1 U15.3(EN)
NetR70_2: R70.2 R71.2
NetR74_1: R74.1 U16.9(EN)
NetR76_1: R76.1 R77.2 U16.7(FB)
NetR79_2: R79.2 U17.2(A)
NetR80_2: R80.2 U17.4(Y)
NetR83_1: R83.1 R84.2 U19.5(VSENSE)
NetR87_1: R87.1 U20.6(VBST)
NetTP40_1: TP40.1 U19.1(EN)

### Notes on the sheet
- (near TP26) +3.3Vsec
- (near TP41) +3.3V

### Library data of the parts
C59 = CMP-0008315-2: CAP, CERM, 10 uF, 10 V, +/- 10%, X7R, 0805; Manufacturer: Samsung Electro-Mechanics; PartNumber: CL21B106KPQNFNE; TaMin_C: -55°C; ESR_ohm: 3m; Polarized: N; SizeAreaWB_mm2: 6.75; Value1: 0.003 ohm; U/M: EA; Value: 10uF; TaMax_C: 125°C; SizeZ_mm: 1.45; SizeX_mm: 2; SizeY_mm: 1.25; Cap_Case: 0805; SizeArea_mm2: 2.5; Cap_F: 10µF; AEC Category: Q200
C60 = C2012X7R1V475K125AC: CAP, CERM, 4.7 µF, 35 V, +/- 10%, X7R, 0805; Manufacturer: TDK; Polarized: N; CompType: Capacitor; Value: 4.7uF; U/M: EA; Cap_F: 0.0000047; Tolerance_%: 10; ESR_ohm: 0.002346; Value1: 0.002346 ohm; VDC_V: 35; Value2: 35V; IRMS_A: 4.26021; TaMin_C: -55; TaMax_C: 125; Cap_Case: 0805; AEC Category: Q200; SizeArea_mm2: 2.5; SizeAreaWB_mm2: 6.75; SizeX_mm: 2; SizeY_mm: 1.25; SizeZ_mm: 1.45
C61 = CMP-0008802-2: CAP, CERM, 10 uF, 50 V, +/- 10%, X7R, 1206; Manufacturer: Samsung; TaMin_C: -55°C; Polarized: N; SizeAreaWB_mm2: 10.92; Value1: Unknown; U/M: EA; Value: 10uF; TaMax_C: 125°C; SizeZ_mm: 1.8; SizeX_mm: 3.2; SizeY_mm: 1.6; Cap_Case: 1206; SizeArea_mm2: 5.12; Cap_F: 10µF; AEC Category: Q200
C62 = CMP-0009026-2: CAP, CERM, 4.7 uF, 50 V, +/- 10%, X7R, 1206_190; Manufacturer: Taiyo Yuden; TaMin_C: -55°C; Polarized: N; SizeAreaWB_mm2: 10.92; Value1: Unknown; U/M: EA; Value: 4.7uF; TaMax_C: 125°C; SizeZ_mm: 1.9; SizeX_mm: 3.2; SizeY_mm: 1.6; Cap_Case: 1206; SizeArea_mm2: 5.12; Cap_F: 4.7µF; AEC Category: Q200
C63 = CMP-0007449-4: CAP, CERM, 330 pF, 50 V, +/- 10%, X7R, 0603; Manufacturer: Samsung Electro-Mechanics; PartNumber: CL10B331KB8NNNC; TaMin_C: -55°C; Polarized: N; SizeAreaWB_mm2: 4.68; Value1: Unknown; U/M: EA; Value: 330pF; TaMax_C: 125°C; SizeZ_mm: 1; SizeX_mm: 1.6; SizeY_mm: 0.8; SizeArea_mm2: 1.28; AEC Category: Q200
C64 = 06035A6R8CAT2A: CAP, CERM, 6.8 pF, 50 V,+/- 4%, C0G/NP0, 0603; Manufacturer: AVX; Polarized: N; CompType: Capacitor; Value: 6.8pF; U/M: EA; Cap_F: 0.0000000000068; Tolerance_%: 4; ESR_ohm: 0.505; Value1: 0.505 ohm; VDC_V: 50; Value2: 50V; TaMin_C: -55; TaMax_C: 125; SizeArea_mm2: 1.28; SizeAreaWB_mm2: 4.68; SizeX_mm: 1.6; SizeY_mm: 0.8; SizeZ_mm: 1; AEC Category: Q200; Green_Lifecycle: Active; Green_REACh: Passed
C65 = C1608X7R1H104K080AA: CAP, CERM, 0.1 µF, 50 V, +/- 10%, X7R, 0603; Manufacturer: Samsung Electro-Mechanics; Polarized: N; CompType: Capacitor; Value: 0.1uF; U/M: EA; Cap_F: 0.0000001; Tolerance_%: 10; ESR_ohm: 0.0296; Value1: 0.0296 ohm; VDC_V: 50; Value2: 50V; IRMS_A: 0.97199; TaMin_C: -55; TaMax_C: 125; SizeArea_mm2: 1.28; SizeAreaWB_mm2: 4.68; SizeX_mm: 1.6; SizeY_mm: 0.8; SizeZ_mm: 1; AEC Category: Q200
C66 = CMP-0008705-2: CAP, CERM, 10 uF, 35 V, +/- 10%, X7R, 1206; Manufacturer: TDK; TaMin_C: -55°C; ESR_ohm: 2.229m; Polarized: N; SizeAreaWB_mm2: 10.92; Value1: 0.002229 ohm; U/M: EA; Value: 10uF; TaMax_C: 125°C; SizeZ_mm: 1.8; SizeX_mm: 3.2; SizeY_mm: 1.6; SizeArea_mm2: 5.12; Cap_F: 10µF; IRMS_A: 4.85932A; AEC Category: Q200
C67 = CMP-0008422-2: CAP, CERM, 0.22 uF, 50 V, +/- 10%, X7R, 0805; Manufacturer: Taiyo Yuden; TaMin_C: -55°C; Polarized: N; SizeAreaWB_mm2: 6.75; Value1: Unknown; U/M: EA; Value: 0.22uF; TaMax_C: 125°C; SizeZ_mm: 1.45; SizeX_mm: 2; SizeY_mm: 1.25; Cap_Case: 0805; SizeArea_mm2: 2.5; Cap_F: 220nF; AEC Category: Q200
C68-C71 = CMP-0008805-2: CAP, CERM, 22 uF, 16 V, +/- 20%, X7R, 1206_190; Manufacturer: Taiyo Yuden; TaMin_C: -55°C; Polarized: N; SizeAreaWB_mm2: 10.92; Value1: Unknown; U/M: EA; Value: 22uF; TaMax_C: 125°C; SizeZ_mm: 1.9; SizeX_mm: 3.2; SizeY_mm: 1.6; Cap_Case: 1206; SizeArea_mm2: 5.12; Cap_F: 22µF; AEC Category: Q200
C72 = CMP-0007119-4: CAP, CERM, 0.1 uF, 16 V, +/- 10%, X7R, 0603; Manufacturer: Taiyo Yuden; TaMin_C: -55°C; Polarized: N; SizeAreaWB_mm2: 4.68; Value1: Unknown; U/M: EA; Value: 0.1uF; TaMax_C: 125°C; SizeZ_mm: 1; SizeX_mm: 1.6; SizeY_mm: 0.8; SizeArea_mm2: 1.28; Cap_F: 100nF; AEC Category: Q200
C73 = 885012206052: CAP, CERM, 1 µF, 16 V,+/- 10%, X7R, 0603; Manufacturer: Wurth Elektronik; Polarized: N; CompType: Capacitor; Value: 1uF; U/M: EA; Cap_F: 0.000001; Tolerance_%: 10; Value1: Unknown; VDC_V: 16; Value2: 16V; TaMin_C: -55; TaMax_C: 125; SizeArea_mm2: 1.28; SizeAreaWB_mm2: 4.68; SizeX_mm: 1.6; SizeY_mm: 0.8; SizeZ_mm: 1; AEC Category: Q200; Green_Lifecycle: Active; Green_REACh: Passed
C74 = 06033C104JAT2A: 0.1µF ±10% 35V Ceramic Capacitor X5R 0603; Manufacturer: Taiyo Yuden; Polarized: N; Value: 0.1uF; U/M: EA; Cap_F: 0.0000001; Tolerance_%: 5; ESR_ohm: 0.05; Value1: 0.05 ohm; VDC_V: 25; Value2: 25V; TempCo: X7R; TaMin_C: -55; TaMax_C: 125; SizeArea_mm2: 1.28; SizeAreaWB_mm2: 4.68; SizeX_mm: 1.6; SizeY_mm: 0.8; SizeZ_mm: 1; AEC Category: Q200
C76 = C2012X5R1E475K125AB: CAP, CERM, 4.7 µF, 25 V, +/- 10%, X5R, 0805; Manufacturer: TDK; Polarized: N; CompType: Capacitor; Value: 4.7uF; U/M: EA; Cap_F: 0.0000047; Tolerance_%: 10; Value1: Unknown; VDC_V: 25; Value2: 25V; TaMin_C: -55; TaMax_C: 85; Cap_Case: 0805
C77 = C2012X5R0J226M: CAP, CERM, 22 µF, 6.3 V, +/- 20%, X5R, 0805; Manufacturer: Samsung Electro-Mechanics; Polarized: N; CompType: Capacitor; Value: 22uF; U/M: EA; Cap_F: 0.000022; Tolerance_%: 20; ESR_ohm: 0.0018; Value1: 0.0018 ohm; VDC_V: 6.3; Value2: 6.3V; TaMin_C: -55; TaMax_C: 85; Cap_Case: 0805
C78 = GRM188R70J104KA01D: CAP, CERM, 0.1 µF, 6.3 V, +/- 10%, X7R, 0603; Manufacturer: KEMET; Polarized: N; CompType: Capacitor; Value: 0.1uF; U/M: EA; Cap_F: 0.0000001; Tolerance_%: 10; Value1: Unknown; VDC_V: 6.3; Value2: 6.3V; TaMin_C: -55; TaMax_C: 125; AEC Category: Q200
C79 = 885012206071: CAP, CERM, 0.1 µF, 25 V, +/- 10%, X7R, 0603; Manufacturer: Wurth Elektronik; Polarized: N; CompType: Capacitor; Value: 0.1uF; U/M: EA; Cap_F: 0.0000001; Tolerance_%: 10; Value1: Unknown; VDC_V: 25; Value2: 25V; TaMin_C: -55; TaMax_C: 125; AEC Category: Q200
C80 = GMK316AB7106KL: CAP, CERM, 10 µF, 35 V, +/- 10%, X7R, 1206; Manufacturer: Taiyo Yuden; Polarized: N; CompType: Capacitor; Value: 10uF; U/M: EA; Cap_F: 0.00001; Tolerance_%: 10; Value1: Unknown; VDC_V: 35; Value2: 35V; TaMin_C: -55; TaMax_C: 125; AEC Category: Q200
C81 = C3216X5R1E476M160AC: as C88 on sheet TIDA-010055-E1_Non-ISO_Communication_PS_Pg4
C82 C83 = GRM21BZ71A226ME15L: CAP, CERM, 22 µF, 10 V, +/- 20%, X7R, 0805; Manufacturer: Samsung Electro-Mechanics; Polarized: N; CompType: Capacitor; Value: 22uF; U/M: EA; Cap_F: 0.000022; Tolerance_%: 20; Value1: Unknown; VDC_V: 10; Value2: 10V; TaMin_C: -55; TaMax_C: 125; Cap_Case: 0805; AEC Category: Q200
C84 = GRM1885C1H220JA01D: CAP, CERM, 22 pF, 50 V, +/- 5%, C0G/NP0, 0603; Manufacturer: Samsung Electro-Mechanics; Polarized: N; CompType: Capacitor; Value: 22pF; U/M: EA; Cap_F: 0.000000000022; Tolerance_%: 5; Value1: Unknown; VDC_V: 50; Value2: 50V; TaMin_C: -55; TaMax_C: 125; AEC Category: Q200
D2 = CMP-0028547-1: Diode, Schottky, 30 V, 1 A, SOD-123; Manufacturer: ON Semiconductor; Io_A: 1A; Green_Lifecycle: Active; SizeAreaWB_mm2: 13.095; Vr_V: 30V; Green_REACh: Passed; TJmax_C: 125°C; U/M: EA; Value: 30V; SizeZ_mm: 1.35; SizeX_mm: 3.85; SizeY_mm: 1.7; Vf_V: 4.7dV; Value2: 0.47V; SizeArea_mm2: 6.545; AEC Category: Q101; RJC_CperW: 108
D3 = LG M67K-G1J2-24-Z: LED, Green, SMD; Manufacturer: OSRAM; SymbolCreator: Altium; Type: AlInGaP; Vf_V: 1.8; Value2: 1.8V; Io_A: 0.002; Vr_V: 12; Tjmax_C: 125; Value1: W; Angle: 120; U/M: EA
L9 = CMP-0058727-1: Inductor, Wirewound, Ferrite, 2.2 uH, 2.6 A, 0.036 ohm, SMD; Manufacturer: MuRata; Isat: 4A @ 30% inductance drop; Irms: 2.6A @ 40C rise; SizeAreaWB_mm2: 34.81; DCR_ohm: 0.036; Value: 2.2uH; Imax_A: 2.6A; SizeZ_mm: 2.2; SizeX_mm: 4.9; SizeArea_mm2: 24.01; Ind_H: 2.2µH; AEC Qualified: N; AEC Category: Q200
L10 = CMP-0064520-2: Inductor, Shielded Drum Core, Metal Composite, 22 uH, 3 A, 0.038 ohm, TH; Manufacturer: Wurth Elektronik; Isat: 3A @ 10% inductance drop; Irms: 3.7A @ 40C rise; Green_Lifecycle: Active; SizeAreaWB_mm2: 169; DCR_ohm: 0.038; Green_REACh: Passed; Value: 22uH; Imax_A: 3A; SizeZ_mm: 11.5; SizeX_mm: 11; SizeArea_mm2: 121; Ind_H: 22µH; AEC Category: Q200
L11 = CMP-0064666-2: Inductor, Shielded, Metal Composite, 11 uH, 5.3 A, 0.014 ohm, SMD; Manufacturer: Wurth Elektronik; Isat: 5.3A @ 10% inductance drop; Irms: 6.9A @ 40C rise; Green_Lifecycle: Active; SizeAreaWB_mm2: 148.84; DCR_ohm: 0.014; Green_REACh: Passed; Value: 11uH; Imax_A: 5.3A; SizeZ_mm: 6.4; SizeX_mm: 10.2; SizeArea_mm2: 104.04; Ind_H: 11µH; AEC Category: Q200
L12 = 74408943220: Inductor, Shielded Drum Core, Ferrite, 22 µH, 1.1 A, 0.185 ohm, SMD; Manufacturer: Wurth Elektronik; Ind_H: 22.0E-6; ValueDisplayed: 22µH; Imax_A: 1.1; Irms: 1.1A @ 40C rise; Isat: 1.4A @ 35% inductance drop; DCR_ohm: 0.185; Value2: 1.1A
L13 = ABG03A15M4R7: Inductor, 4.7 µH, 1.12 A, 0.12 ohm, SMD; Manufacturer: Coilank; Value: 4.7uH; Ind_H: 4.7E-6; Imax_A: 1.12; Irms: 1.12A @ 40C rise; Isat: 1.13A @ 35% inductance drop; DCR_ohm: 0.12; Value2: 1.12A; AEC Category: Q200; AEC Qualified: N; SizeAreaWB_mm2: 16; SizeArea_mm2: 9; SizeX_mm: 3; SizeZ_mm: 1.5
L14 = ABG06A45M3R3: Inductor, 3.3 µH, 3.91 A, 0.026 ohm, SMD; Manufacturer: Coilank; Value: 3.3uH; Ind_H: 3.3E-6; Imax_A: 3.91; Irms: 3.81A @ 40C rise; Isat: 6.08A @ 35% inductance drop; DCR_ohm: 0.026; Value2: 3.91A; AEC Category: Q200; AEC Qualified: N; SizeAreaWB_mm2: 64; SizeArea_mm2: 36; SizeX_mm: 6; SizeZ_mm: 4.5
Q1 = CSD17571Q2: MOSFET, N-CH, 30 V, 22 A, DQK0006C (WSON-6); Manufacturer: Texas Instruments; Alternate Manufacturer: None; U/M: EA; ChType: N; Value: 30V; VdsMax_V: 30; Value1: 0.029 ohm; Rdson45_ohm: 0.029; Value2: 2.4 nC; QgTyp_nC: 2.4; Vgs_V: 20; IdsMax_A: 22; SizeAreaWB_mm2: 9; SizeArea_mm2: 4; SizeX_mm: 2; SizeZ_mm: 0.8; AEC Category: Q101
R54 R63 R68 R82 R85 R86 = 5108: as R51 on sheet TIDA-010055-E1_Non-ISO_Communication_PS_Pg4
R64 R67 R69 R75 R76 = CMP-0023363-3: RES, 100 k, 0.1%, 0.1 W, AEC-Q200 Grade 0, 0603; Manufacturer: Panasonic; Power_W: 100mW; TempCo: 25 ppm/C; U/M: EA; Value: 100k; EIA_Code: E192; SizeX_mm: 1.6; SizeY_mm: 0.8; SizeZ_mm: 1; Value2: 0.1W; SizeArea_mm2: 1.28; AEC Qualified: Y; VDC_V: 75V; AEC Grade: 0; AEC Category: Q200
R65 = CMP-0019302-2: RES, 475 k, 0.5%, 0.1 W, 0805; Manufacturer: Susumu Co Ltd; Power_W: 100mW; TempCo: 25 ppm/C; U/M: EA; Value: 475k; EIA_Code: E192; SizeX_mm: 2; SizeY_mm: 1.25; SizeZ_mm: 1.45; Value2: 0.1W; SizeArea_mm2: 2.5; VDC_V: 100V; AEC Category: Q200
R66 = RC0603FR-07453KL: RES, 453 k, 1%, 0.1 W, 0603; Manufacturer: Yageo America; CompType: Resistor; Value: 453k; Res_ohm: 453000; Tolerance_%: 1; Power_W: 0.1; Value2: 0.1W; VDC_V: 150; TempCo: 200 ppm/C; SizeArea_mm2: 1.28; SizeX_mm: 1.6; SizeY_mm: 0.8; EIA_Code: E96; U/M: EA; AEC Category: Q200
R70 = CMP-0019636-2: RES, 182 k, 0.1%, 0.125 W, 0805; Manufacturer: Yageo America; Power_W: 125mW; TempCo: 25 ppm/C; U/M: EA; Value: 182k; EIA_Code: E192; SizeX_mm: 2; SizeY_mm: 1.25; SizeZ_mm: 1.45; Value2: 0.125W; SizeArea_mm2: 2.5; CompType: Resistor; VDC_V: 150V; AEC Category: Q200
R71 R72 R74 = CMP-0023343-3: RES, 0, 1%, 0.1 W, AEC-Q200 Grade 0, 0603; Manufacturer: Stackpole Electronics Inc; Power_W: 100mW; TempCo: ppm/C; U/M: EA; Value: 0; SizeX_mm: 1.6; SizeY_mm: 0.8; SizeZ_mm: 1; Value2: 0.1W; SizeArea_mm2: 1.28; AEC Qualified: Y; AEC Category: Q200
R73 = CMP-0023404-3: RES, 10.0 k, 0.1%, 0.1 W, 0603; Manufacturer: Susumu Co Ltd; Power_W: 100mW; TempCo: 25 ppm/C; Value_Code: 10k0; U/M: EA; Value: 10.0k; EIA_Code: E192; Res_ohm: 10k; SizeX_mm: 1.6; SizeY_mm: 0.8; SizeZ_mm: 1; Value2: 0.1W; SizeArea_mm2: 1.28; VDC_V: 75V; AEC Category: Q200
R77 = CMP-0023990-3: RES, 24.9 k, 0.1%, 0.1 W, 0603; Manufacturer: Yageo America; Power_W: 100mW; TempCo: 25 ppm/C; Value_Code: 24k9; U/M: EA; Value: 24.9k; EIA_Code: E192; SizeX_mm: 1.6; SizeY_mm: 0.8; SizeZ_mm: 1; Value2: 0.1W; SizeArea_mm2: 1.28; CompType: Resistor; VDC_V: 75V; AEC Category: Q200
R78 R80 = CRCW0603300RJNEA: RES, 300, 5%, 0.1 W, 0603; Manufacturer: Vishay-Dale; CompType: Resistor; Value: 300; Value_Code: 300R; Tolerance_%: 5; Power_W: 0.1; Value2: 0.1W; VDC_V: 75; TempCo: 200 ppm/C; SizeArea_mm2: 1.28; SizeX_mm: 1.6; SizeY_mm: 0.8; SizeZ_mm: 1; EIA_Code: E24; U/M: EA; AEC Category: Q200
R79 = RMCF0603ZT0R00: RES, 0, 1%, 0.1 W, AEC-Q200 Grade 0, 0603; Manufacturer: Stackpole Electronics Inc; CompType: Resistor; Value: 0; Tolerance_%: 1; Power_W: 0.1; Value2: 0.1W; TempCo: ppm/C; SizeArea_mm2: 1.28; SizeX_mm: 1.6; SizeY_mm: 0.8; U/M: EA; AEC Category: Q200; AEC Qualified: Y
R83 = CRCW060361K9FKEA: RES, 61.9 k, 1%, 0.1 W, 0603; Manufacturer: Vishay-Dale; CompType: Resistor; Value: 61.9k; Res_ohm: 61900; Value_Code: 61k9; Tolerance_%: 1; Power_W: 0.1; Value2: 0.1W; VDC_V: 75; TempCo: 100 ppm/C; EIA_Code: E96; U/M: EA
R84 = CRCW060320K0FKEA: RES, 20.0 k, 1%, 0.1 W, 0603; Manufacturer: Vishay-Dale; CompType: Resistor; Value: 20.0k; Res_ohm: 20000; Value_Code: 20k0; Tolerance_%: 1; Power_W: 0.1; Value2: 0.1W; VDC_V: 75; TempCo: 100 ppm/C; EIA_Code: E96; U/M: EA
R87 = CRCW06030000Z0EA: as R97-R103 on sheet TIDA-010055-E1_Non-ISO_Communication_PS_Pg4
R88 = CRCW060380K6FKEA: RES, 80.6 k, 1%, 0.1 W, 0603; Manufacturer: Vishay-Dale; CompType: Resistor; Value: 80.6k; Res_ohm: 80600; Value_Code: 80k6; Tolerance_%: 1; Power_W: 0.1; Value2: 0.1W; VDC_V: 75; TempCo: 100 ppm/C; EIA_Code: E96; U/M: EA; AEC Category: Q200; SizeArea_mm2: 1.28; SizeX_mm: 1.6; SizeY_mm: 0.8; Green_Lifecycle: Active; Green_REACh: Passed
R89 = CRCW060333K2FKEA: RES, 33.2 k, 1%, 0.1 W, 0603; Manufacturer: Vishay-Dale; CompType: Resistor; Value: 33.2k; Res_ohm: 33200; Value_Code: 33k2; Tolerance_%: 1; Power_W: 0.1; Value2: 0.1W; VDC_V: 75; TempCo: 100 ppm/C; EIA_Code: E96; U/M: EA; AEC Category: Q200; SizeArea_mm2: 1.28; SizeX_mm: 1.6; SizeY_mm: 0.8; Green_Lifecycle: Active; Green_REACh: Passed
R90 = CRCW060351R0JNEA: RES, 51, 5%, 0.1 W, 0603; Manufacturer: Vishay-Dale; CompType: Resistor; Value: 51; Value_Code: 51R0; Tolerance_%: 5; Power_W: 0.1; Value2: 0.1W; VDC_V: 75; TempCo: 200 ppm/C; EIA_Code: E24; U/M: EA; AEC Category: Q200
R91 = CRCW060349K9FKEA: RES, 49.9 k, 1%, 0.1 W, 0603; Manufacturer: Vishay-Dale; CompType: Resistor; Value: 49.9k; Res_ohm: 49900; Value_Code: 49k9; Tolerance_%: 1; Power_W: 0.1; Value2: 0.1W; VDC_V: 75; TempCo: 100 ppm/C; EIA_Code: E96; U/M: EA; AEC Category: Q200; SizeArea_mm2: 1.28; SizeX_mm: 1.6; SizeY_mm: 0.8; Green_Lifecycle: Active; Green_REACh: Passed
R92 = RCG060310K0FKEA: RES, 10.0 k, 1%, 0.1 W, 0603; Manufacturer: Vishay Draloric; CompType: Resistor; Value: 10.0k; Res_ohm: 10000; Value_Code: 10k0; Tolerance_%: 1; Power_W: 0.1; Value2: 0.1W; VDC_V: 75; TempCo: 100 ppm/C; EIA_Code: E96; U/M: EA; AEC Category: Q200; AEC Qualified: N; SizeArea_mm2: 1.28; SizeX_mm: 1.6; SizeY_mm: 0.8
TP26 TP41 = 5000: Test Point, Miniature, Red, TH; Manufacturer: Keystone; CompType: Test Point Loop; U/M: EA
TP28 TP30 TP32 TP35 TP36 TP40 TP42 = 5002: as TP14 on sheet TIDA-010055-E1_Non-ISO_Communication_PS_Pg4
TP29 TP33 = 5000: Test Point, Miniature, Red, TH; Manufacturer: Keystone; CompType: Test Point Loop; ContactFinish: Silver; Green_Lifecycle: Active; Green_REACh: Passed
TP31 TP34 TP39 = 5001: as TP16 on sheet TIDA-010055-E1_Non-ISO_Communication_PS_Pg4
TP37 = CMP-0055138-1: Test Point, Miniature, Black, TH; Manufacturer: Keystone; CNHeader: FALSE; Green_Lifecycle: Active; Green_REACh: Passed; ContactFinish: Silver; CT: TRUE
U14 = CMP-0013407-3: 2-A High Efficiency Step-Down Converter in SOT Package, DRL0006A (SOT-6); Manufacturer: Texas Instruments; SizeZ_mm: 0.6; SizeX_mm: 1.6; SizeArea_mm2: 2.56; CompType: IC; U/M: EA; SizeAreaWB_mm2: 6.76
U15 = CMP-0072695-3: 520kHz/1.6MHz - Space-Efficient Boost and SEPIC DC-DC Regulator, 6-pin LLP, Pb-Free; Manufacturer: Texas Instruments; PackageTopMarking: ZXYTT*2735X; CompType: Switcher; PowerWise: N; High-Reliability: Y
U16 = CMP-0065235-5: 3.8-V to 36-V 2-A Synchronous Step-Down Voltage Regulator, RNX0012B (VQFN-HR-12); Manufacturer: Texas Instruments; Alternate PartNumber: LMR33630ARNXT; SizeX_mm: 2.0; SizeY_mm: 3.0; CompType: IC; SizeZ_mm: 1.0; SizeArea_mm2: 6.0; SizeAreaWB_mm2: 12.0; AEC Category: Q200; AEC Qualified: N
U17 = SN74LVC1G17DCKR: SINGLE SCHMITT-TRIGGER BUFFER, DCK0005A (SOT-SC70-5); Alternate PartNumber: SN74LVC1G17DCKT; Manufacturer: Texas Instruments; SymbolCreator: a0799628; SizeArea_mm2: 4.2; SizeAreaWB_mm2: 9.3; SizeX_mm: 2.1; SizeY_mm: 2; SizeZ_mm: 1.1; CompType: IC; U/M: EA
U19 = TPS560200DBV: 4.5V to 18V Input, 500mA Synchronous Step Down SWIFT Converter with Advanced Eco-mode, DBV0005A; Manufacturer: Texas Instruments; SymbolCreator: a0411947; CompType: IC; U/M: EA
U20 = TPS561201DDCR: 4.5-V to 17-V Input, 2-A Synchronous Step-Down Voltage Regulator, DDC0006A (SOT-23-T-6); Alternate PartNumber: TPS561201DDCT; Manufacturer: Texas Instruments; SymbolCreator: a0411947; CompType: IC; U/M: EA; SizeArea_mm2: 4.8675; SizeAreaWB_mm2: 10.4675; SizeX_mm: 1.65; SizeY_mm: 2.95; SizeZ_mm: 0.87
